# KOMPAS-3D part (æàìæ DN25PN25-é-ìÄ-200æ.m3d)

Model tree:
1. Объединить компоненты:1  (labels: СЕНС DN25PN25-В-НО-200С)

Referenced files in D:\Савин\!СЕНСОР\3D для заказчика\!Новый перечень\СЕНС\7. СЕНС-В-НО-200С\DN25\: СЕНС DN25PN25-В-НО-200С.a3d
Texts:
  СЕНС DN25PN25-В-НО-200С
  ООО НПП Сенсор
